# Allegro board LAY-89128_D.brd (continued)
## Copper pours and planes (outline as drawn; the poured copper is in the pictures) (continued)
VBUS_DC on TOP: 158.09,51.51 158.76,50.85 160.56,50.85 160.74,51.02 160.74,51.65 160.89,51.8 161.93,51.8 162.31,51.43 162.31,50.97 162.31,50.96 162.31,48.83 161.92,48.44 157.04,48.44 156.82,48.67 156.82,50.98 157.35,51.51
VBUS_DC on BOTTOM: 158.19,50.93 156.67,50.93 156.54,50.8 156.54,48.77 156.67,48.64 157.94,48.64 158.44,49.15 158.44,50.67
VBUS_PA on TOP: 176.71,51.94 173.71,51.94 173.33,51.56 173.33,49.35 173.56,49.12 175.74,49.12 176.07,48.79 176.07,48.44 176.3,48.21 177.11,48.21 177.16,48.26 177.16,51.49
VDDIO on TOP: 104.8,39.92 103.91,39.92 103.91,37.11 104.15,36.87 104.53,36.87 104.8,37.13
VDDIO on TOP: 111.38,42.85 110.34,42.85 109.68,42.19 106.98,42.19 106.58,41.78 106.58,40.46 106.96,40.08 110.9,40.08 111.38,40.56
VDDIO on L3_INT_1: 113.26,43.76 112.06,43.76 111.97,43.68 109.16,43.68 105.79,40.31 104.09,40.31 103.68,39.9 103.68,36.88 104.02,36.54 109.13,36.54 113.61,41.02 113.61,43.41
VDDIO_BRD on TOP: 112.17,42.85 115.77,42.85 116.74,43.81 121.49,43.81 121.61,43.69 121.61,42.42 121.49,42.29 119.94,42.29 118.57,40.92 116.66,40.92 116.46,40.72 116.46,39.65 116.1,39.29 114.07,39.29 112.01,41.35 112.01,42.7
VDDIO_BRD on TOP: 172.06,14.43 171.35,14.43 171.17,14.25 171.17,12.73 170.33,11.89 170.33,10.19 170.48,10.03 172.87,10.03 173.23,10.39 173.23,12.14 172.31,13.06 172.31,14.17
VDDIO_BRD on L3_INT_1: 115.52,41.4 115.01,41.4 109.49,35.88 103.9,35.88 101.93,33.91 96.85,33.91 94.18,31.24 94.18,4.83 98.37,0.63 172.67,0.63 174.45,2.41 174.45,14.35 174.32,14.48 172.92,14.48 171.02,12.57 171.02,11.81 170.38,11.18 163.78,11.18 158.19,5.59 112.85,5.59 111.07,3.81 100.15,3.81 98.75,5.21 98.75,10.29 102.82,14.35 114.88,14.35 115.52,14.99 115.52,16.76 115.26,17.02 113.11,17.02 111.96,18.16 111.96,34.92 115.77,38.73 115.77,41.15
(no net) on BOTTOM: outline of 162 points within 76.91,0.63 185.52,59.37 ; 13 cut-outs
DC5V on L3_INT_1: 150.57,25.15 150.57,23.24 150.95,22.86 152.48,22.86 152.6,22.99 152.6,25.91 153.62,26.92 153.62,32.89 151.59,34.92 127.84,34.92 126.82,33.91 126.82,31.88 127.58,31.12 144.35,31.12 146.13,29.34 146.13,26.16 146.51,25.78 149.94,25.78
J_VBATPWR on TOP: 100.79,42.74 101.07,42.46 105.69,42.46 105.71,42.44 106.45,42.44 107.03,43.03 107.03,44.5 108.46,45.92 113.89,45.92 114.13,46.16 114.13,49.06 113.49,49.7 106.6,49.7 106.04,49.15 101.07,49.15 100.79,48.87
J_VBATPWR on BOTTOM: 102.95,48.64 102.95,45.5 102.55,45.11 102.26,44.82 102.26,43.87 102.47,43.66 103.07,43.66 103.14,43.73 105.31,43.73 105.54,43.51 105.54,42.65 105.69,42.49 106.42,42.49 106.7,42.77 106.7,45.34 107.09,45.72 112.47,45.72 113.36,46.61 113.36,49.02 112.85,49.53 103.83,49.53
J_VUP on TOP: 99.7,49.07 100.02,48.75 100.02,42.46 93.87,42.46 93.87,42.47 92.05,42.47 91.73,42.79 91.73,48.62 92.18,49.07
J_VUP on BOTTOM: 96.77,43.99 99.1,43.99 99.33,44.22 99.33,44.24 101.11,46.02 101.11,48.69 100.73,49.07 96.99,49.07 96.54,48.62 96.54,44.22
MCU_VDD on TOP: 117.27,39.11 115.98,39.11 115.74,38.87 115.74,37.37 115.9,37.21 116.46,37.21 116.51,37.16 116.51,36.7 116.71,36.5 117.04,36.5 117.22,36.68 117.22,37.36 117.51,37.66 117.51,38.87
MCU_VDD on BOTTOM: 117.55,39.5 116.53,39.5 116.41,39.37 116.41,38.35 116.28,38.23 115.14,38.23 115.01,38.1 115.01,37.59 115.39,37.21 117.17,37.21 117.8,37.85 117.8,39.24
MCU_VDD on L3_INT_1: 117.04,50.55 121.11,50.55 122.88,48.77 122.88,38.73 120.6,36.45 120.6,32.77 122.12,31.24 122.12,29.21 120.73,27.81 114.38,27.81 114.12,27.56 113.36,27.56 113.23,27.69 113.23,35.31 116.41,38.48 116.41,49.91
Net_134 on TOP: 15.2,50.5 15.2,44.9 9.6,44.9 9.6,50.5
Net_135 on TOP: 44.7,15.1 44.7,9.5 39.1,9.5 39.1,15.1
Net_136 on TOP: 38.8,15.1 38.8,9.5 33.2,9.5 33.2,15.1
Net_137 on TOP: 32.9,15.1 32.9,9.5 27.3,9.5 27.3,15.1
Net_138 on TOP: 27,15.1 27,9.5 21.4,9.5 21.4,15.1
Net_139 on TOP: 21.1,15.1 21.1,9.5 15.5,9.5 15.5,15.1
Net_140 on TOP: 9.3,15.1 9.3,9.5 3.7,9.5 3.7,15.1
Net_141 on TOP: 15.2,15.1 15.2,9.5 9.6,9.5 9.6,15.1
Net_142 on TOP: 44.7,26.9 44.7,21.3 39.1,21.3 39.1,26.9
Net_143 on TOP: 44.7,21 44.7,15.4 39.1,15.4 39.1,21
Net_144 on TOP: 38.8,26.9 38.8,21.3 33.2,21.3 33.2,26.9
Net_145 on TOP: 32.9,26.9 32.9,21.3 27.3,21.3 27.3,26.9
Net_146 on TOP: 38.8,21 38.8,15.4 33.2,15.4 33.2,21
Net_147 on TOP: 32.9,21 32.9,15.4 27.3,15.4 27.3,21
Net_148 on TOP: 27,26.9 27,21.3 21.4,21.3 21.4,26.9
Net_149 on TOP: 27,21 27,15.4 21.4,15.4 21.4,21
Net_150 on TOP: 21.1,26.9 21.1,21.3 15.5,21.3 15.5,26.9
Net_151 on TOP: 21.1,21 21.1,15.4 15.5,15.4 15.5,21
Net_152 on TOP: 9.3,26.9 9.3,21.3 3.7,21.3 3.7,26.9
Net_153 on TOP: 15.2,26.9 15.2,21.3 9.6,21.3 9.6,26.9
Net_154 on TOP: 15.2,21 15.2,15.4 9.6,15.4 9.6,21
Net_155 on TOP: 9.3,21 9.3,15.4 3.7,15.4 3.7,21
Net_156 on TOP: 44.7,38.7 44.7,33.1 39.1,33.1 39.1,38.7
Net_157 on TOP: 44.7,32.8 44.7,27.2 39.1,27.2 39.1,32.8
Net_158 on TOP: 38.8,38.7 38.8,33.1 33.2,33.1 33.2,38.7
Net_159 on TOP: 38.8,32.8 38.8,27.2 33.2,27.2 33.2,32.8
Net_160 on TOP: 32.91,38.7 32.91,33.1 27.31,33.1 27.31,38.7
Net_161 on TOP: 32.9,32.8 32.9,27.2 27.3,27.2 27.3,32.8
Net_162 on TOP: 27,38.7 27,33.1 21.4,33.1 21.4,38.7
Net_163 on TOP: 27,32.8 27,27.2 21.4,27.2 21.4,32.8
Net_164 on TOP: 21.1,38.7 21.1,33.1 15.5,33.1 15.5,38.7
Net_165 on TOP: 21.1,32.8 21.1,27.2 15.5,27.2 15.5,32.8
Net_166 on TOP: 9.3,38.7 9.3,33.1 3.7,33.1 3.7,38.7
Net_167 on TOP: 9.3,32.8 9.3,27.2 3.7,27.2 3.7,32.8
Net_168 on TOP: 15.2,38.7 15.2,33.1 9.6,33.1 9.6,38.7
Net_169 on TOP: 15.2,32.8 15.2,27.2 9.6,27.2 9.6,32.8
Net_170 on TOP: 38.8,44.6 38.8,39 33.2,39 33.2,44.6
Net_171 on TOP: 32.9,44.6 32.9,39 27.3,39 27.3,44.6
Net_172 on TOP: 27,44.6 27,39 21.4,39 21.4,44.6
Net_173 on TOP: 21.1,44.6 21.1,39 15.5,39 15.5,44.6
Net_174 on TOP: 9.3,44.6 9.3,39 3.7,39 3.7,44.6
Net_175 on TOP: 15.2,44.6 15.2,39 9.6,39 9.6,44.6
Net_176 on TOP: 44.7,44.6 44.7,39 39.1,39 39.1,44.6
Net_177 on TOP: 44.7,50.5 44.7,44.9 39.1,44.9 39.1,50.5
Net_178 on TOP: 38.8,50.5 38.8,44.9 33.2,44.9 33.2,50.5
Net_179 on TOP: 32.9,50.5 32.9,44.9 27.3,44.9 27.3,50.5
Net_180 on TOP: 27,50.5 27,44.9 21.4,44.9 21.4,50.5
Net_181 on TOP: 21.1,50.5 21.1,44.9 15.5,44.9 15.5,50.5
Net_182 on TOP: 9.3,50.5 9.3,44.9 3.7,44.9 3.7,50.5
SDA_USBSHIELD on TOP: 181.96,47.12 185.14,47.12 185.47,46.79 185.47,44.68 185.34,44.55 183.84,44.55 183.79,44.6 183.79,45.29 183.72,45.36 182.98,45.36 182.92,45.3 182.92,43.68 182.78,43.54 181.23,43.54 181.15,43.61 181.15,45.47 181.86,46.18 181.86,47.02
SDA_USBSHIELD on TOP: 182.65,39.6 181.41,39.6 181.15,39.34 181.15,36.6 181.76,35.99 181.76,32.87 182.07,32.56 185.09,32.56 185.47,32.94 185.47,38.13 185.29,38.3 183.84,38.3 183.77,38.23 183.77,37.59 183.62,37.44 182.93,37.44 182.88,37.49 182.88,39.37
SDA_USBSHIELD on BOTTOM, L2_GND_1: 184.86,47.75 181.81,47.75 181.69,47.62 181.69,33.66 182.45,32.89 184.99,32.89 185.24,33.15 185.24,47.37
USB_5V_DC on TOP: 149.53,48.97 153.26,48.97 153.62,48.62 153.62,44.98 151.41,44.98 151.41,43.31 150.9,42.8 146.63,42.8 143.15,39.32 143.15,34.24 143.53,33.86 150.67,33.86 151.05,33.48 151.05,23.06 150.67,22.68 147.37,22.68 146.99,23.06 146.99,26.06 145.46,27.58 138.91,27.58 138.53,27.97 138.53,35.94 138.77,36.18 138.77,43.55 139.78,44.55 139.78,44.58 148.41,44.58 149.15,45.31 149.15,48.59
USB_5V_DC on BOTTOM: 155.14,50.93 156.03,50.93 156.16,50.8 156.16,48.64 153.87,46.35 150.19,46.35 149.81,46.74 149.81,49.53 150.19,49.91 154.13,49.91
USB_5V_DC on L3_INT_1: 123.01,36.07 121.49,36.07 121.11,35.69 121.11,33.02 122.5,31.62 122.5,29.34 121.11,27.94 121.11,24.38 123.2,22.29 148.86,22.29 149.94,23.37 149.94,24.26 148.92,25.27 147.14,25.27 146,24.13 141.17,24.13 139.65,25.65 126.69,25.65 123.71,28.64 123.71,32.7 123.14,33.27 123.14,35.94
USB_5V_PA on TOP: 177.72,48.03 177.72,49.05 177.75,49.07 179.78,49.07 181.1,50.39 185.27,50.39 185.5,50.16 185.5,48.46 185.09,48.06 181.76,48.06 181.2,47.5 178.81,47.5 178.15,46.84 177.24,46.84 177.11,46.96 177.11,47.42
USB_5V_PA on L3_INT_1: 184.23,51.05 179.91,51.05 179.02,50.16 179.02,47.75 180.35,47.75 182.54,45.56 182.54,35.98 176.67,30.1 168.6,30.1 163.4,24.89 153.49,24.89 153.36,24.77 153.36,23.62 154.38,22.61 157.3,22.61 158.57,21.34 166.83,21.34 167.84,22.35 167.84,26.04 168.99,27.18 176.22,27.18 176.86,27.81 181.69,27.81 184.61,30.73 184.61,50.67
USB_DC_SHLD on TOP: 154.71,59.36 164.99,59.36 165.18,59.18 165.18,55.85 166.34,54.69 166.34,52.25 165.91,51.82 163.27,51.82 163.14,51.94 163.14,56.9 162.84,57.2 156.89,57.2 156.36,56.66 156.36,52.5 156.23,52.37 154.61,52.37 154.45,52.53 154.45,59.11
USB_DC_SHLD on BOTTOM, L2_GND_1, L3_INT_1: 154.71,59.36 164.99,59.36 165.18,59.18 165.18,52.43 165.12,52.37 165.12,52.02 164.92,51.82 163.27,51.82 163.14,51.94 163.14,56.9 162.84,57.2 156.89,57.2 156.36,56.66 156.36,52.5 156.23,52.37 154.61,52.37 154.45,52.53 154.45,59.11
USB_PA_SHLD on TOP: 170.03,59.33 180.26,59.33 180.8,58.8 180.8,55.98 182.35,54.43 182.35,52.15 181.89,51.69 179.02,51.69 178.45,52.26 178.45,55.82 178.13,56.13 172.03,56.13 171.75,55.85 171.75,51.92 171.65,51.82 170.26,51.82 168.96,53.11 168.96,58.26
USB_PA_SHLD on BOTTOM, L2_GND_1, L3_INT_1: 170.03,59.33 180.26,59.33 180.8,58.8 180.8,55.5 180.77,55.47 180.77,52.04 180.42,51.69 179.02,51.69 178.45,52.26 178.45,55.82 178.13,56.13 172.03,56.13 171.75,55.85 171.75,51.92 171.65,51.82 170.26,51.82 169.85,52.22 169.85,59.15
V_TGTMCU on L3_INT_1: 157.94,51.43 132.03,51.43 126.82,46.23 126.82,38.55 127.25,38.12 128.91,38.12 129.38,37.65 139.7,37.65 146.68,44.63 146.69,44.63 146.95,44.89 160.7,44.89 160.93,44.66 160.93,43 160.92,42.99 160.92,42.92 159.77,41.77 159.77,41.68 157.28,39.19 157.28,35.15 158.7,33.73 172.15,33.73 172.55,34.13 172.55,34.63 172.3,34.89 165.55,34.89 164.4,36.03 162.67,36.03 161.84,36.86 161.84,37.23 161.59,37.47 160.17,37.47 159.81,37.83 159.81,39.12 160.34,39.64 160.41,39.64 161.85,41.08 161.86,41.08 161.86,42.6 161.95,42.69 162.23,42.69 162.51,42.97 162.51,43.69 162.25,43.95 162.25,47.12 162,47.37 161.43,47.37 161.14,47.09 161.14,46.03 160.77,45.66 158.21,45.66 158.07,45.52 156.77,45.52 156.61,45.68 156.61,47.7 158.06,49.15 158.06,51.31
VMAIN on TOP: 148.51,16.33 147.57,16.33 147.52,16.38 147.52,21.74 147.95,22.17 154.71,22.17 154.76,22.12 154.76,20.42 154.41,20.07 148.89,20.07 148.69,19.86 148.69,16.51
VMAIN on TOP: 165.35,16.46 169.95,16.46 170.23,16.74 170.23,18.39 169.8,18.82 165.15,18.82 164.97,18.64 164.97,16.84
VMAIN on TOP: 165.45,24.51 171.4,24.51 171.93,25.04 171.93,26.82 171.27,27.48 165.33,27.48 164.95,27.1 164.95,25.02
VMAIN on BOTTOM: 101.93,9.02 123.01,9.02 125.04,11.05 136.22,11.05 136.6,10.67 136.6,5.46 135.71,4.57 113.74,4.57 113.11,5.21 101.68,5.21 101.55,5.33 101.55,8.64
VMAIN on BOTTOM: 169.95,16.46 170.23,16.74 170.23,18.39 169.8,18.82 168.35,18.82 167.97,18.44 167.97,17.78 167.59,17.4 165.1,17.4 165.05,17.35 165.05,16.46
VMAIN on BOTTOM: 155.02,22.48 147.9,22.48 147.52,22.1 147.52,16.51 147.78,16.26 148.41,16.26 148.67,16.51 148.67,17.27 149.05,17.65 155.02,17.65 155.52,18.16 155.52,21.97
VMAIN on BOTTOM: 165.18,24.51 171.4,24.51 171.93,25.04 171.93,26.82 171.27,27.48 168.48,27.48 168.22,27.23 168.22,26.04 167.97,25.78 165.07,25.78 164.95,25.65 164.95,24.74
VMAIN on L3_INT_1: 169.87,15.24 157.56,15.24 151.97,9.65 131.39,9.65 131.01,10.03 131.01,16.26 131.9,17.14 147.27,17.14 148.16,18.03 148.16,21.72 148.41,21.97 157.56,21.97 158.7,20.83 167.59,20.83 168.22,21.46 168.22,25.65 169.49,26.92 170.89,26.92 171.65,26.16 171.65,17.02
VUP on TOP: 94.23,40.43 94.76,40.43 95.02,40.18 95.02,38.65 95.14,38.53 95.78,38.53 95.91,38.65 95.91,41.6 95.67,41.83 94.11,41.83 93.87,41.6 93.87,40.79
VUP on BOTTOM: 95.79,40.43 95.79,42.35 95.91,42.46 95.91,45.64 95.62,45.92 94.3,45.92 93.87,45.49 93.87,40.56 94.25,40.18 95.53,40.18
VUP on L3_INT_1: 95.27,41.83 95.51,41.59 95.51,37.86 95.04,37.38 81.38,37.38 79.65,39.12 78.31,39.12 77.93,39.5 77.93,41.91 78.31,42.29 94.81,42.29

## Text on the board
BOTTOM: 07 | L4_SS | 170-89128 REV D
Board Geometry/Soldermask Bottom: 08 | SECONDARY SOLDERMASK
Ref Des/Silkscreen Bottom: A | 1 | J27 | 2 | GND | IRQ | MS_SP | SPI_SCK | SPI_PCS | SPI_MISO | SPI_MOSI | MS/YEL_LED | MS_SP_DONE | VEN/GRN_LED | 09 | SECONDARY SILKSCREEN
User.Comments: 1 OF 1 | TEST PROBE | 1/1 | 1 | 2
TOP: 04 | L1_PS
Ref Des/Assembly Top: 3
Board Geometry/Soldermask Top: 03 | PRIMARY SOLDERMASK
Ref Des/Silkscreen Top: CONTACT INTERFACE-J13 | CONTACT INTERFACE-J12 | CONTACT INTERFACE-J14 | CONTACT INTERFACE-J15 | MICRO-C USB | iMX8 BOARD INTERFACE | GPIO3 | AUX1 | AUX2 | 3 | 2 | JTAG | USB-TYPE C | 02 | PRIMARY SILKSCREEN | PNEV7220BP2-4.0
L2_GND_1: 05 | L2_GND_1
L3_INT_1: 06 | L3_INT_1
XSECTION_CHART: LAYERS | L1_PS | L4_SS | TRACE WIDTH | 19.88 | SE | IMPEDANCE | 20.00 | 4.25 | TRACE SPACING | 5.55 | DIFF | 90.00 | REFERENCE LAYER | 2 | SCALE: NONE | ALL VALUES ARE FINISHED VALUES. | BOARD THICKNESS TOLERANCE +/-10% | 23. | 22 | INTENTIONAL 9 SHORTS AT: | LocationStart     LocationEnd       RefDes       Net 1                Net 2 | (1244.50 1546.00) (1307.50 1546.00)     SH1       VDDIO               VDDIO_BRD | (1540.00 1388.63) (1540.00 1451.63)     SH6       MCU_VBAT            VDDIO_BRD | (1466.50 1405.00) (1403.50 1405.00)     SH5       MCU_VDD             VDDIO_BRD | (1690.00 1146.27) (1690.00 1083.27)     SH4       MCU_VDDA            MCU_VDD | (1556.06 881.00) (1619.06 881.00)       SH3       3V3_VDD             SH_3V3_VDDIO_E | (1630.41 1646.48) (1693.41 1646.48)     SH2       K82_JTAG_RST        RST_TGTMCU_B | (2121.50 1500.00) (2184.50 1500.00)     SH7       VDDIO_BRD           V_TGTMCU | (2632.00 1682.35) (2632.00 1782.35)     J58       SDA_RST_TGTMCU_B    SDA_RST_TGTMCU_J_B | (3756.04 1634.75) (3756.04 1734.75)     J61       SDA_VOUT33          P3V3_SDA | 19 | 16 | *  SURFACE - AIR 0 MIL | *  DIELECTRIC - DRY_FILM_MASK 1.4 MIL | L1 TOP CONDUCTOR - COPPER 0.48 MIL | *  DIELECTRIC - FR4 2.95 MIL | L2 L2_GND_1 PLANE - 1/2OZ_COPPER 0.7 MIL | *  DIELECTRIC - FR4 51.2 MIL | L3 L3_INT_1 CONDUCTOR - 1/2OZ_COPPER 0.7 MIL | L4 BOTTOM CONDUCTOR - COPPER 0.48 MIL | DETAIL | IMPEDANCE REQUIREMENTS | IMPEDANCE TOLERANCE IS 10% | LAYER STACKUP | DESIGN CROSS SECTION CHART | ___________________________ | TOTAL THICKNESS 62.259 MIL | 1-4 | B | A
DIMENSION: ONLY ON BOTTOM SIDE 2x | 1/3 PCB THICKNESS | BREAKING EDGE | DETAIL-C | TOP SIDE | BOT SIDE | 1.01 +/-0.1 mm | X8 | PRIMARY DATUM | GRID ORIGIN
BODY_CENTER: 01 | PRIMARY PASTEMASK
DISPLAY_TOP: 10 | SECONDARY PASTEMASK
User.9: 1 | 4 | 7 | 14 | 56 | 15 | 28 | 43 | 42 | 29 | H | A | 8
User.10: ON | 1 | 2 | 4 | 3 | SH4 | SH1 | B12 | A1 | A2 | B11 | A3 | B10 | A4 | B9 | A5 | B8 | A6 | B7 | B6 | A7 | B5 | A8 | B4 | A9 | B3 | A10 | B2 | A11 | A12 | B1 | SH2 | SH3 | 24 | 23 | 22 | 21 | 20 | 5 | 12 | 11 | 19 | 6 | 10 | 18 | 7 | 9 | 17 | 8 | 16 | 15 | 14 | 13 | 32 | 31 | 30 | 29 | 33 | 28 | 27 | 26 | 25 | 39 | 40 | 37 | 38 | 35 | 36 | 34 | 100 | 99 | 98 | 97 | 96 | 95 | 94 | 93 | 92 | 91 | 90 | 89 | 88 | 101 | 87 | 86 | 41 | 85 | 42 | 84 | 43 | 83 | 44 | 82 | 45 | 81 | 46 | 80 | 47 | 79 | 48 | 78 | 49 | 77 | 50 | 76 | 75 | 74 | 73 | 72 | 71 | 70 | 69 | 68 | 67 | 66 | 65 | 64 | 63 | 62 | 61 | 60 | 59 | 58 | 57 | 56 | 55 | 54 | 53 | 52 | 51 | C | A | B | C2 | C1 | S2 | S1 | C3 | C7 | C6 | C5 | H8 | G8 | F8 | E8 | D8 | C8 | H7 | G7 | F7 | E7 | D7 | H6 | G6 | F6 | E6 | D6 | H5 | G5 | F5 | E5 | D5 | H4 | G4 | F4 | E4 | D4 | C4 | H3 | G3 | F3 | E3 | D3 | H2 | G2 | F2 | E2 | D2 | H1 | G1 | F1 | E1 | D1 | PCB EDGE SIDE | PCB EDGE | SMART CARD INSERTION AREA | 2022 NXP B.V. | + | -
User.11: C5 | C7 | 1 | C1 | C3 | 9 | 16 | 8 | 17 | 10 | 24 | 32 | 25 | 2 | 4 | 5 | 3 | C4 | C8 | SMART CARD INSERTION AREA | PCB EDGE SIDE | 2021 NXP B.V.
User.12: ON | PCB EDGE SIDE | PCB EDGE | SMART CARD INSERTION AREA | 2022 NXP B.V. | 1 | 4 | 7 | 9 | 2 | 10 | 5 | 6 | 14 | 16 | 56 | 15 | 8 | 12 | 25 | 32 | 24 | H1 | H8 | 3 | 17 | A1 | A8 | 43 | 28 | 42 | 29 | C7 | C3 | C5 | C1 | 13 | 76 | 100 | 75 | 51 | 50 | 26 | A12 | B1 | B12 | C8 | C4 | 39 | 40 | B | A | C | + | -
User.16: 6501 WILLIAM CANNON DRIVE WEST | AUSTIN. TEXAS 78735 USA | SHEET | THIS DOCUMENT CONTAINS INFORMATION | PROPRIETARY TO NXP AND SHALL NOT | BE USED FOR ENGINEERING DESIGN | PROCUREMENT OR MANUFACTURE IN WHOLE | OR IN PART WITHOUT THE CONSENT OF | NXP. | FILM | NAME | DATE | 05-11-21 | ___ COMPANY PUBLIC | ___ COMPANY INTERNAL | ___ COMPANY CONFIDENTIAL | NUMBER | 4 OF 12 | L1_PS | X | 170-32196      REV B1 | X-PNEV5190BP | NXP SEMICONDUCTORS
User.18: 14 | 1 | 56 | 15 | 28 | 43 | 42 | 29 | A | B | 2 | 7 | 10 | 8 | 4 | 3 | 9 | 5 | B1 | A12 | A1 | B12 | be aware of the Header Size | In case of JTAG Application, | PCB EDGE | 2023 NXP B.V. | +
User.19: 1 | J61 | 1.9000 | 54.0000 | 4.0000 | 31.5000 | 9.0000 | 19.6205 | 24.7005 | 85.0000 | 77.0000 | 18.3419 | 20.8819
User.20: PCB EDGE SIDE | 1 | 10 | 20 | 11 | 2 | 3 | 8 | 7 | B1 | A1 | C | A | 5 | B18 | A18 | 13 | 9 | 100 | 99 | 19 | 2018 NXP B.V. | 14 | 39 | 40 | 6 | 4 | PCB EDGE | B12 | A12 | 37 | 48 | 36 | 25 | 24 | 12 | 16
User.21: 14 | 1 | 56 | 15 | 28 | 43 | 42 | 29 | A | B | 2 | 7 | 10 | 8 | 39 | 40 | 3 | 4 | 9 | 5 | B1 | A12 | A1 | B12 | SEE NOTE ON PACKAGE GEOMATRY/NSP_DETAIL_TOP | NOT RECOMMENDED FOR MANUFACTUREING | be aware of the Header Size | In case of JTAG Application, | PCB EDGE | 2024 NXP B.V. | +
User.23: OF 10
User.26: 22. THIS FAB_VIAFILL.ART SHOWS LOCATIONS OF VIA-IN-PAD TO BE FILLED. | 1/1 | 2
User.27: 1/1
User.29: 08-07-24 | 11-07-24 | 09-28-23 | J.Q. | L.C. | G.R. | C.L. | C | B | D | RESPIN | ECO30019337 Changes | ECO175617 Changes
User.34: FIGURE | FINISHED_SIZE | 6.0 | 8.0 | 10.0 | 10.1 | 28.0 | 40.0 | 41.0 | 59.0 | 146.0 | 125.0 | 63.0x23.0 | 82.0x23.0 | DRILL CHART: TOP to BOTTOM | ALL UNITS ARE IN MILS | TOLERANCE_DRILL | +0.0/-6.0 | +0.0/-8.0 | +0.0/-10.0 | +0.0/-10.1 | +2.0/-2.0 | +3.0/-3.0 | PLATED | NON-PLATED | QTY | 4 | 120 | 336 | 137 | 20 | 97 | 54 | 2
